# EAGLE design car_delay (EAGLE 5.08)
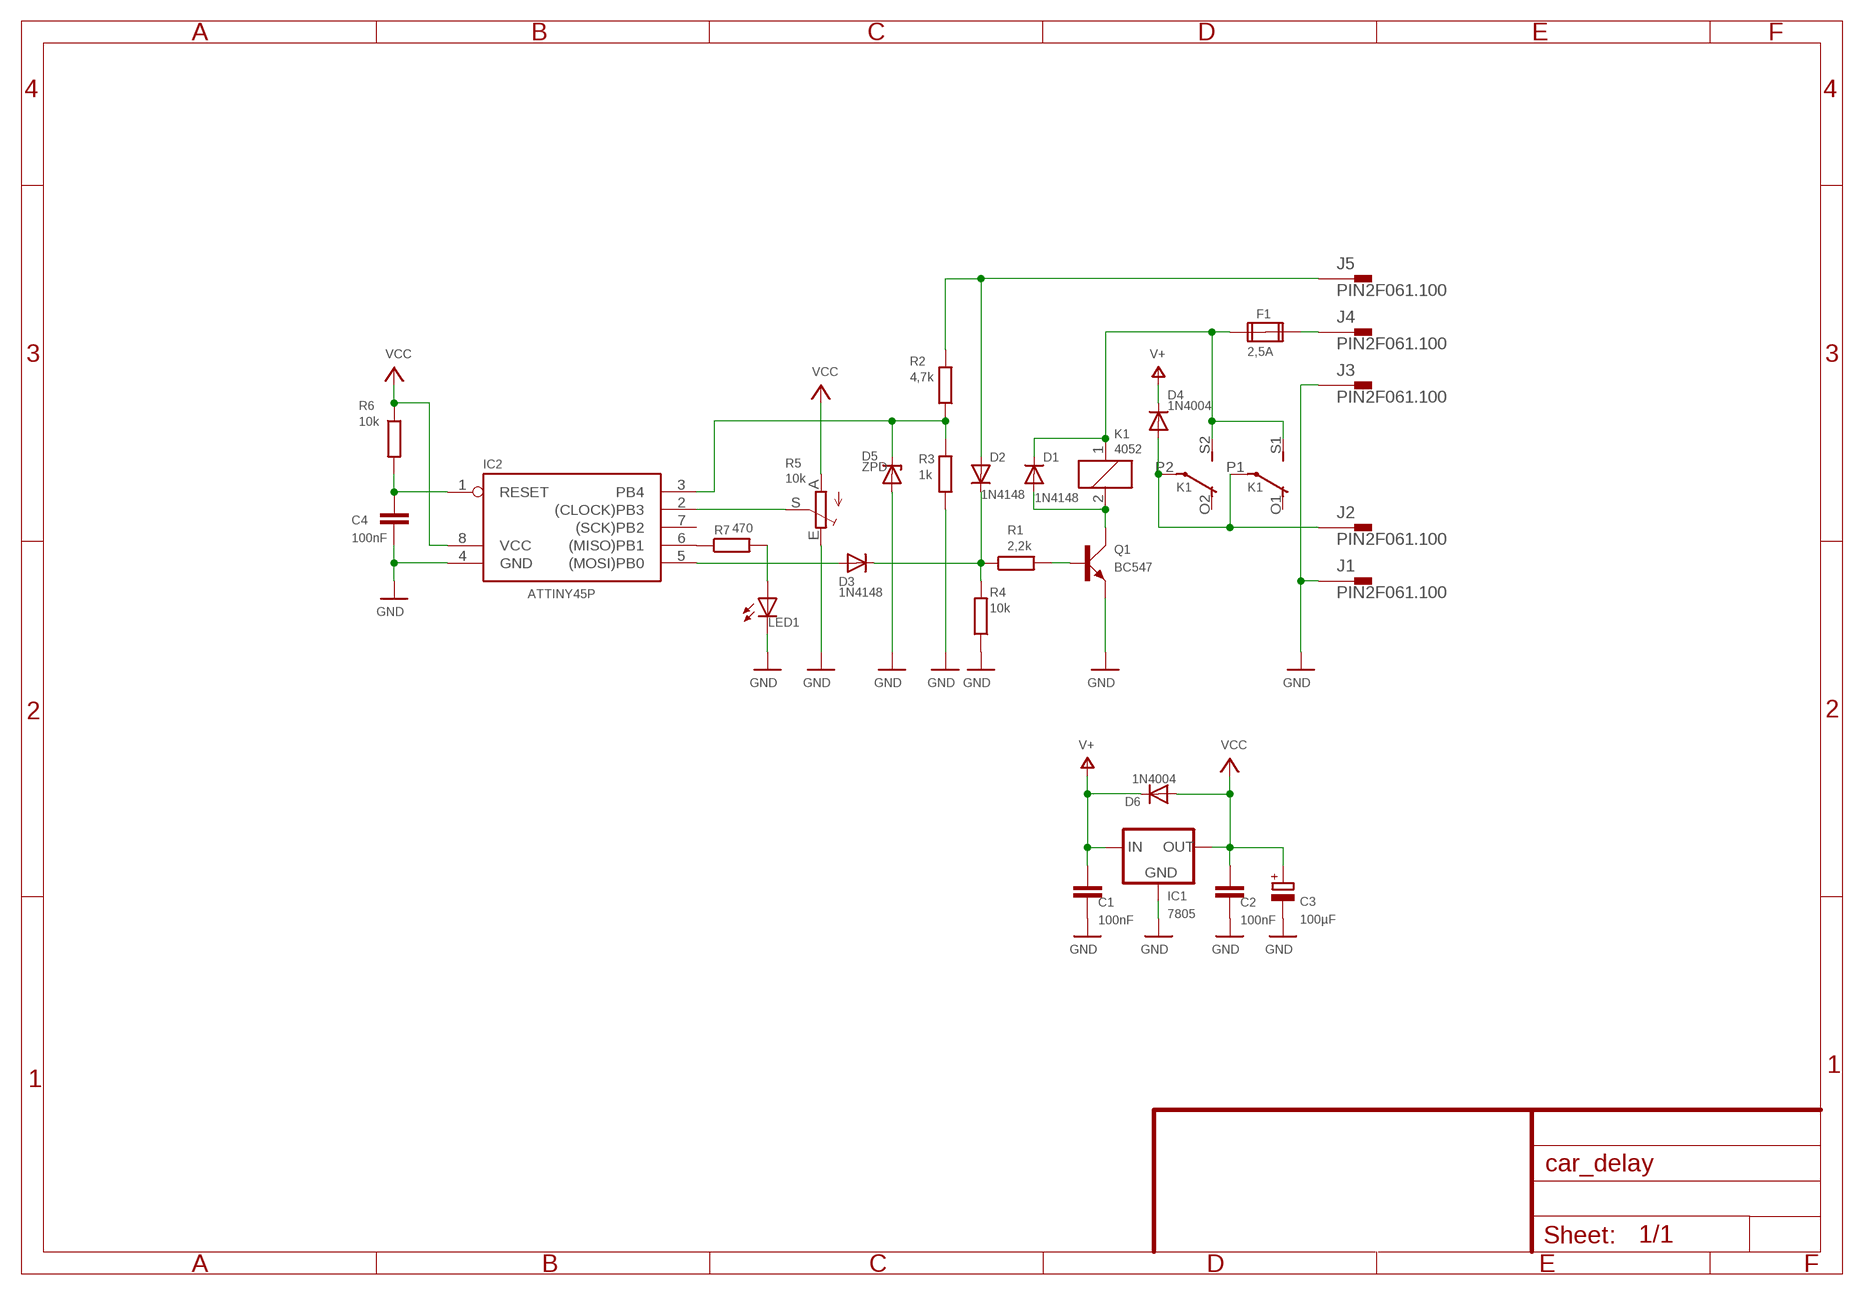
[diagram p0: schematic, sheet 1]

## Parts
C1  100nF  C-EU025-025X050  [C025-025X050]
C2  100nF  C-EU025-025X050  [C025-025X050]
C3  100µF  CPOL-EUE5-8.5  [E5-8,5]
C4  100nF  C-EU025-025X050  [C025-025X050]
D1  1N4148  [DO35-10]
D2  1N4148  [DO35-10]
D3  1N4148  [DO35-10]
D4  1N4004  [DO41-10]
D5  ZPD  [DO35Z10]
D6  1N4004  [DO41-10]
F1  2,5A  FUSE2P  [FUSE1]
IC1  7805  78LXX  [78LXX]
IC2  ATTINY45P  TINY22P  [DIL08]
J1  PIN2F061.100  [F061.100]
J2  PIN2F061.100  [F061.100]
J3  PIN2F061.100  [F061.100]
J4  PIN2F061.100  [F061.100]
J5  PIN2F061.100  [F061.100]
K1  4052  [F4052]
LED1  LED3MM  [LED3MM]
Q1  BC547  [SOT54A]
R1  2,2k  R-EU_0207/10  [0207/10]
R2  4,7k  R-EU_0207/10  [0207/10]
R3  1k  R-EU_0207/10  [0207/10]
R4  10k  R-EU_0207/10  [0207/10]
R5  10k  TRIM_EU-LI10  [LI10]
R6  10k  R-EU_0207/10  [0207/10]
R7  470  R-EU_0207/10  [0207/10]

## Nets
GND: C1.2 C2.2 C3.- C4.2 D5.A IC1.GND IC2.4(GND) J1.A1 J3.A1 LED1.K(C) Q1.E R3.1 R4.1 R5.E
N$1: D1.A K1.2 Q1.C
N$2: F1.2A J4.A1
N$3: D1.C F1.1A K1.1 K1.S1(2:S) K1.S2(3:S)
N$4: Q1.B R1.2
N$5: D2.C D3.C R1.1 R4.2
N$6: D4.A J2.A1 K1.P1(2:P) K1.P2(3:P)
N$7: D2.A J5.A1 R2.2
N$8: D5.C IC2.3(PB4) R2.1 R3.2
N$9: D3.A IC2.5((MOSI)PB0)
N$10: LED1.A R7.2
N$11: IC2.6((MISO)PB1) R7.1
N$13: IC2.2((CLOCK)PB3) R5.S
N$14: C4.1 IC2.1(RESET) R6.2
V+: C1.1 D4.C D6.C IC1.IN
VCC: C2.1 C3.+ D6.A IC1.OUT IC2.8(VCC) R5.A R6.1
Unconnected: F1.1B F1.2B IC2.7((SCK)PB2) J1.A2(1.1) J2.A2(1.1) J3.A2(1.1) J4.A2(1.1) J5.A2(1.1) K1.O1(2:O) K1.O2(3:O)

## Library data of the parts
C1 C2 C4 = rcl:C-EU: CAPACITOR, European symbol
C3 = rcl:CPOL-EU: POLARIZED CAPACITOR, European symbol
D1-D3 = diode:1N4148: DIODE
D4 D6 = diode:1N4004: DIODE
D5 = diode:ZPD: Z DIODE
F1 = special:FUSE2P: FUSE 5 x 20 mm
IC1 = v-reg:78LXX: VOLTAGE REGULATOR
IC2 = atmel:TINY22: MICROCONTROLLER 1K ROM 128 bytes RAM 128 bytes EEPROM
J1-J5 = con-faston:PIN2: Flachstecker Typ Tyco/Electronics/AMP TAB, FASTON
K1 = relay:4052: RELAY 2 x switch, Finder
LED1 = led:LED: LED
Q1 = transistor-small-signal:BC547: NPN TRANSISTOR
R1-R4 R6 R7 = rcl:R-EU_: RESISTOR, European symbol
R5 = pot:TRIM_EU-: POTENTIOMETER

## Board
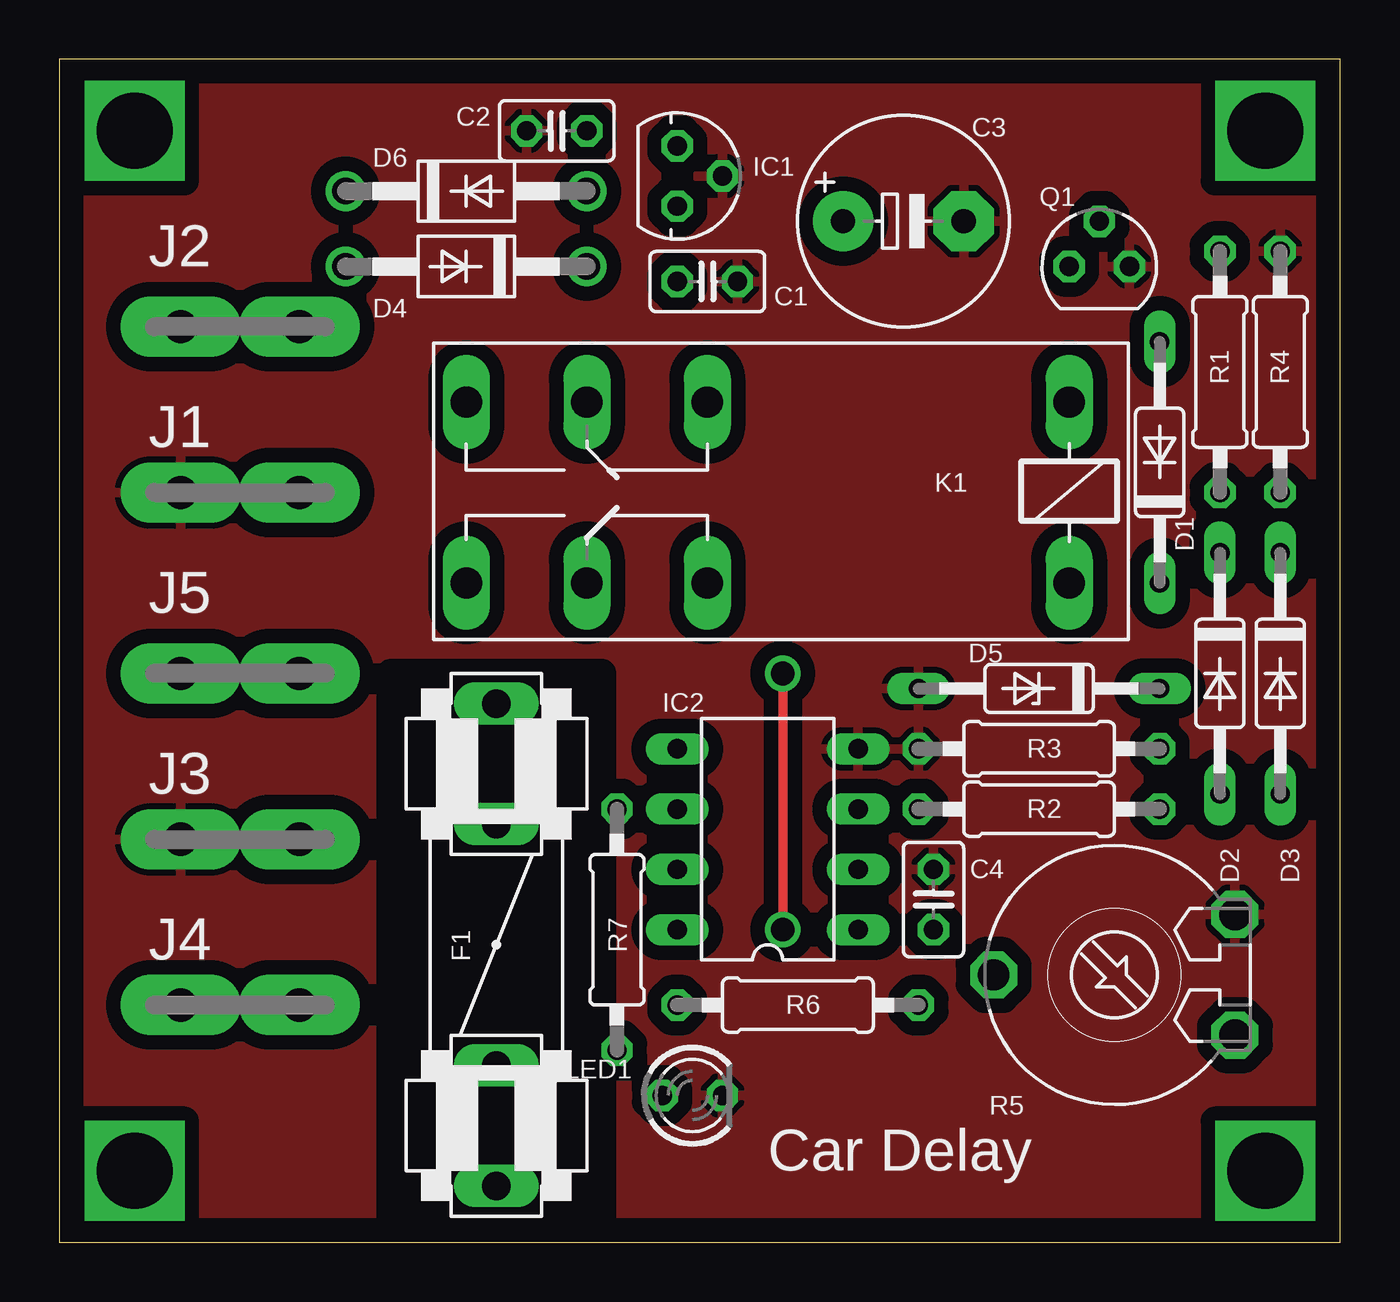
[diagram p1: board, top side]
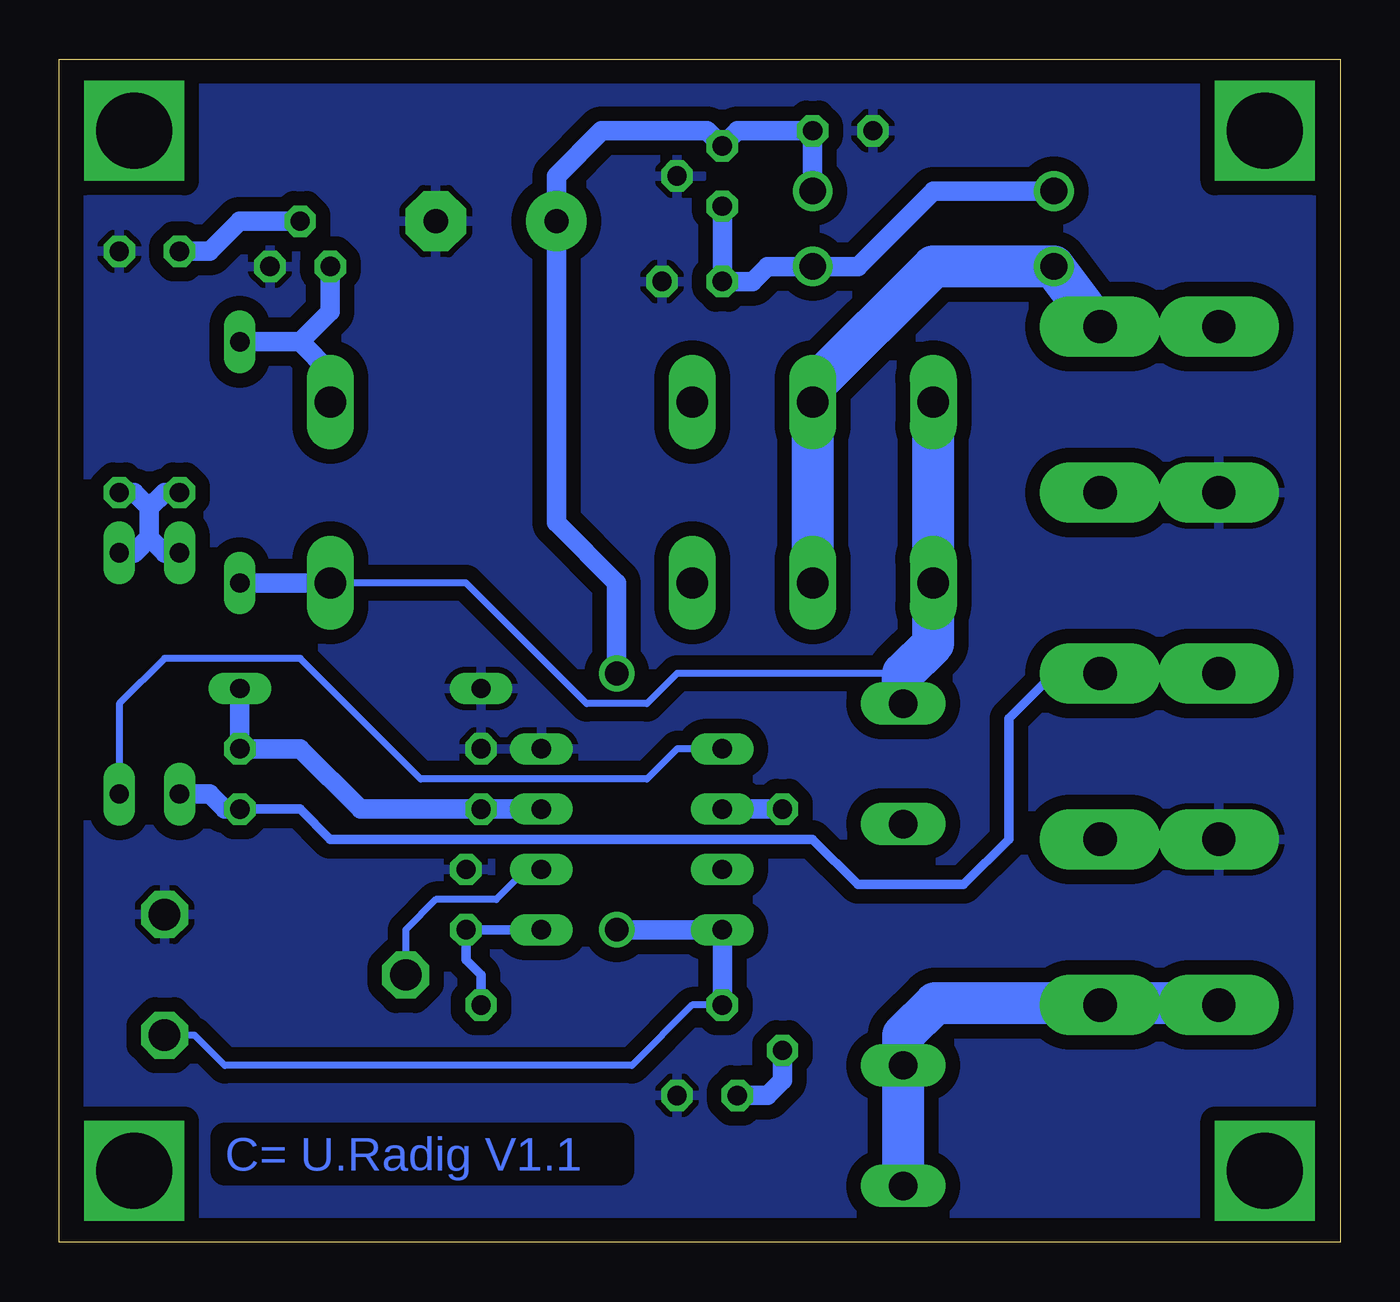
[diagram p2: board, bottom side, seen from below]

Size 53.95 x 49.84 mm. Coordinates in mm from the lower left corner, seen from the top.
Outline: 0,0 53.95,0 53.95,49.84 0,49.84 0,0
Copper layers (1*16): Top 0.035mm / dielectric 1.5mm / Bottom 0.035mm
Design rules "default": minimum track width 10mil, minimum drill 24mil, track to track 8mil, track to pad 8mil, pad to pad 8mil, via to via 8mil, smd to smd 8mil, copper to edge 40mil, drill to drill 8mil, minimum pad ring 10mil, minimum via ring 8mil, stop-mask expansion 4mil, vias tented up to drill 0mil, thermal gap 10mil
tRestrict: area 14,1.1 to 22.9,24

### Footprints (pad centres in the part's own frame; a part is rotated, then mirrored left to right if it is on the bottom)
C025-025X050 = drill 0.813 octagon: 1 -1.27,0; 2 1.27,0
E5-8,5 = drill 1.016 pad 2.54 round: + -2.54,0 | drill 1.016 pad 2.54 octagon: - 2.54,0
DO35-10 = drill 0.813 long: A 5.08,0; C -5.08,0
DO41-10 = drill 1.118 round: A 5.08,0; C -5.08,0
DO35Z10 = drill 0.813 long: A 5.08,0; C -5.08,0
FUSE1 = drill 1.194 long: 1A -10.16,0; 1B -5.08,0; 2A 10.16,0; 2B 5.08,0
78LXX = drill 0.813 octagon: GND 0,1.905; IN 1.27,0; OUT -1.27,0
DIL08 = drill 0.813 long: 1 -3.81,-3.81; 2 -1.27,-3.81; 3 1.27,-3.81; 4 3.81,-3.81; 5 3.81,3.81; 6 1.27,3.81; 7 -1.27,3.81; 8 -3.81,3.81
F061.100 = drill 1.4 pad 2.54 long: A1 -2.5,0; A2 2.5,0
F4052 = drill 1.321 long: 1 -3.81,3.81; 2 -3.81,-3.81; O1 11.43,-3.81; O2 11.43,3.81; P1 16.51,-3.81; P2 16.51,3.81; S1 21.59,-3.81; S2 21.59,3.81
LED3MM = drill 0.813 octagon: A -1.27,0; K 1.27,0
SOT54A = drill 0.813 octagon: B 0,1.905; C -1.27,0; E 1.27,0
0207/10 = drill 0.813 octagon: 1 -5.08,0; 2 5.08,0
LI10 = drill 1.321 octagon: A -2.54,-5.08; E 2.54,-5.08; S 0,5.08

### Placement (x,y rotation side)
C1  27.3,40.48 0 top
C2  20.95,46.83 180 top
C3  35.56,43.02 0 top
C4  36.83,14.44 90 top
D1  46.35,32.86 90 top
D2  48.89,23.96 270 top
D3  51.43,23.96 270 top
D4  17.14,41.11 180 top
D5  41.27,23.33 180 top
D6  17.14,44.29 0 top
F1  18.41,12.54 270 top
IC1  26.03,44.92 270 top
IC2  29.84,16.98 90 top
J1  7.62,31.59 0 top
J2  7.62,38.57 180 top
J3  7.62,16.98 0 top
J4  7.62,10 0 top
J5  7.62,23.96 180 top
K1  38.73,31.59 180 top
LED1  26.66,6.18 0 top
Q1  43.81,41.11 0 top
R1  48.89,36.66 90 top
R2  41.27,18.25 0 top
R3  41.27,20.79 0 top
R4  51.43,36.66 270 top
R5  44.44,11.27 90 top
R6  31.11,10 0 top
R7  23.49,13.17 270 top

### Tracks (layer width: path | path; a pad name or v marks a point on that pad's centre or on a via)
GND
  pour Bottom (isolate 0.61): 0.63,49.37 53.33,49.37 53.33,0.47 0.63,0.47
  pour Top (isolate 0.61): 0.63,49.37 53.33,49.37 53.33,0.47 0.63,0.47
N$1
  Bottom 0.813: 43.81,37.94 42.54,36.66 K1.2 | 43.81,37.94 D1.A | 43.81,37.94 42.54,39.2 Q1.C
N$2
  Bottom 0.406: J4.A1 5.12,10.08
  Bottom 1.778: F1.2A 18.41,8.73 17.06,10.08 5.12,10.08
N$3
  Bottom 0.305: 18.41,23.96 27.93,23.96 29.21,22.7 31.75,22.7 36.83,27.78 K1.1
  Bottom 0.813: K1.1 D1.C
  Bottom 1.778: K1.S1 K1.S2 17.14,25.23 18.41,23.96 F1.1A
N$4
  Bottom 0.813: Q1.B 46.35,43.02 47.62,41.74 R1.2
N$5
  Bottom 0.813: R1.1 49.53,31.59 50.16,30.95 | 50.16,30.95 50.8,31.59 R4.2 | D3.C 50.8,29.05 50.16,29.68 | 50.16,29.68 50.16,30.95 | D2.C 49.53,29.05 50.16,29.68
N$6
  Bottom 0.406: J2.A1 10.12,38.61
  Bottom 0.813: 22.22,36.03 K1.P1 | 10.12,38.61 10.16,38.57
  Bottom 1.778: K1.P1 K1.P2 | 22.22,36.03 17.14,41.11 D4.A 10.16,38.57
N$7
  Bottom 0.406: R2.2 43.81,18.25 42.54,16.98 22.22,16.98 20.32,15.08 15.87,15.08 13.96,16.98 13.96,22.06 12.06,23.96 J5.A1
  Bottom 0.813: R2.2 46.98,18.25 47.62,18.89 D2.A
N$8
  Bottom 0.813: D5.C R3.2 43.81,20.79 41.27,18.25 R2.1 IC2.3
N$9
  Bottom 0.305: D3.A 51.43,22.7 49.53,24.6 43.81,24.6 38.73,19.52 29.21,19.52 27.93,20.79 IC2.5
N$10
  Bottom 0.813: R7.2 23.49,6.82 24.12,6.18 LED1.A
N$11
  Bottom 0.813: R7.1 IC2.6
N$13
  Bottom 0.305: IC2.2 34.28,15.71 35.56,14.44 38.09,14.44 39.36,13.17 R5.S
N$14
  Bottom 0.406: R6.2 36.19,11.27 36.83,11.9 C4.1 IC2.1
N$15  (via drill 3.2)
  other vias: 3.17,46.83
N$16  (via drill 3.2)
  other vias: 50.8,46.83
N$17  (via drill 3.2)
  other vias: 3.17,3.01
N$18  (via drill 3.2)
  other vias: 50.8,3.01
V+
  Bottom 0.813: D6.C 17.14,44.29 20.32,41.11 D4.C 24.12,41.11 24.76,40.48 C1.1 IC1.IN
VCC  (via drill 1)
  Top 0.406: v30.48,13.17 v30.48,23.96
  Bottom 0.305: R5.A 48.25,8.73 46.98,7.46 29.84,7.46 27.3,10 R6.1
  Bottom 0.813: R6.1 IC2.8 v30.48,13.17 | v30.48,23.96 30.48,27.78 33.02,30.32 C3.+ 33.02,44.92 31.11,46.83 26.66,46.83 IC1.OUT 25.39,46.83 C2.1 D6.A

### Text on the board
Bottom: C= U.Radig V1.1
tNames: Car Delay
